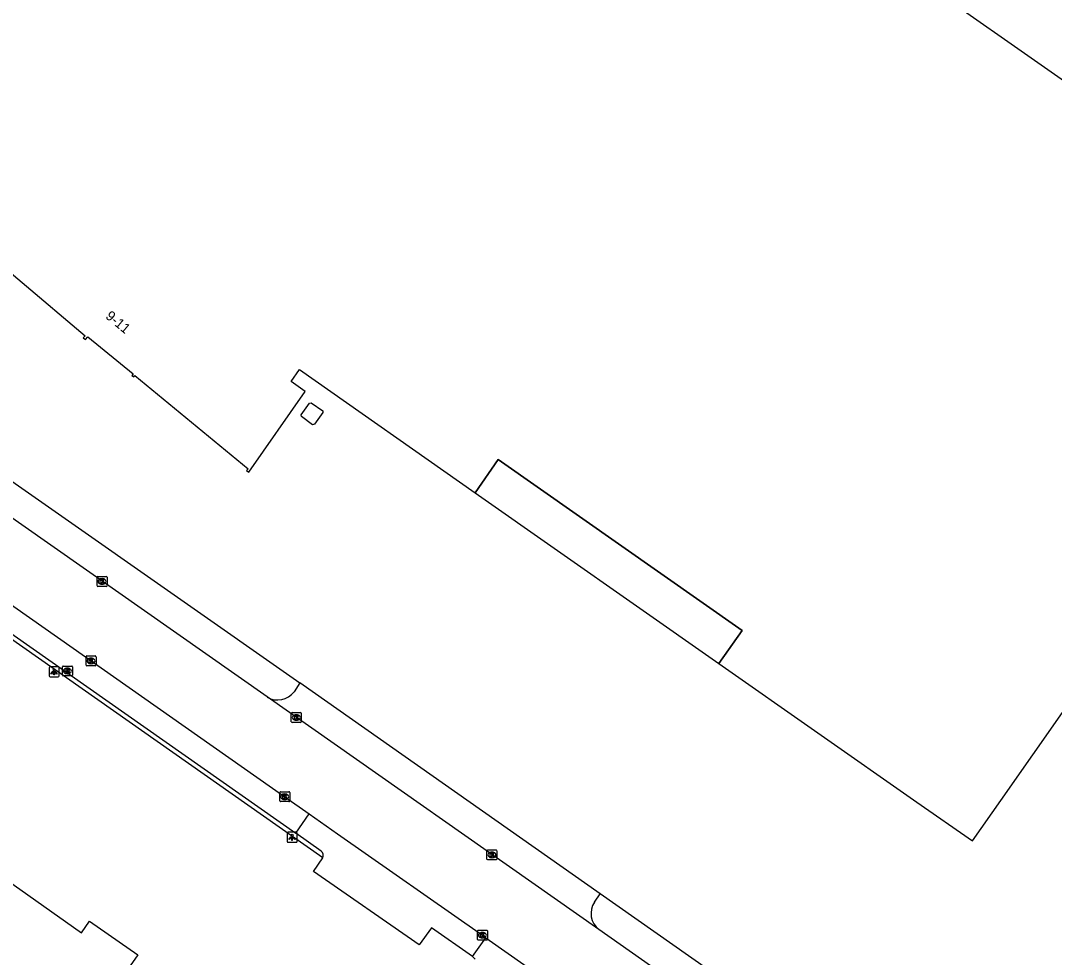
# Model space of a CAD drawing. Extents: x 155018 to 156648, y 383980 to 385733.
# Drawn here: x 155409.7 to 155513.9, y 384753.9 to 384848.3 of the extents above; entities that cross this region are included whole.
import ezdxf

# ---------------------------------------------------------------- set-up
doc = ezdxf.new("R2010")
doc.units = 0
for name, color, linetype in [('IMGEO_Brandkraan', 7, 'Continuous'), ('IMGEO_Kolk', 7, 'Continuous'), ('IMGEO_Lichtpunt', 7, 'Continuous'), ('IMGEO_Pand', 7, 'Continuous'), ('IMGEO_Pand_nummerreeks', 7, 'Continuous'), ('IMGEO_Pand_overbouw', 7, 'Continuous'), ('IMGEO_Parkeervlak_open', 7, 'Continuous'), ('IMGEO_Rijbaan_lokaal_gesloten', 7, 'Continuous'), ('IMGEO_Voetpad_open', 7, 'Continuous')]:
    doc.layers.add(name, color=color, linetype=linetype)

msp = doc.modelspace()

# ---------------------------------------------------------------- linework, layer by layer
at = {"layer": 'IMGEO_Brandkraan'}
for p, q in [((155413.94, 384782.3), (155413.94, 384783.16)), ((155414.02, 384783.23), (155414.87, 384783.23)), ((155414.43, 384783.01), (155414.45, 384783.01)), ((155414.94, 384783.16), (155414.94, 384782.3)), ((155414.87, 384782.23), (155414.02, 384782.23)), ((155414.45, 384782.45), (155414.43, 384782.45))]:
    msp.add_line(p, q, dxfattribs=at)
for points in [[(155413.94, 384782.3), (155413.94, 384783.16)], [(155414.02, 384783.23), (155414.87, 384783.23)], [(155414.94, 384783.16), (155414.94, 384782.3)], [(155414.87, 384782.23), (155414.02, 384782.23)], [(155414.29, 384782.93), (155414.29, 384782.53), (155414.5, 384782.53)], [(155414.52, 384782.93), (155414.29, 384782.93)], [(155414.47, 384782.85), (155414.41, 384782.85), (155414.41, 384782.77)], [(155414.41, 384782.77), (155414.47, 384782.77)], [(155414.48, 384782.7), (155414.41, 384782.7), (155414.41, 384782.61)], [(155414.41, 384782.61), (155414.48, 384782.61)]]:
    msp.add_lwpolyline(points, dxfattribs=at)
for centre, radius, start, end in [((155414.02, 384783.15), 0.0765, 91.552, 178.448), ((155414.02, 384783.15), 0.0765, 91.552, 178.448), ((155414.87, 384783.15), 0.0765, 1.552, 88.448), ((155414.87, 384783.15), 0.0765, 1.552, 88.448), ((155414.02, 384782.3), 0.0765, 181.552, 268.448), ((155414.02, 384782.3), 0.0765, 181.552, 268.448), ((155414.47, 384782.81), 0.0379, 267.8285, 90.9355), ((155414.48, 384782.66), 0.0404, 269.8759, 90.5077), ((155414.51, 384782.78), 0.251, 268.6676, 293.5347), ((155414.52, 384782.78), 0.145, 59.4692, 91.5367), ((155414.55, 384782.83), 0.0922, 285.5137, 58.1501), ((155414.55, 384782.64), 0.105, 301.3115, 78.989), ((155414.87, 384782.3), 0.0765, 271.552, 358.448), ((155414.87, 384782.3), 0.0765, 271.552, 358.448)]:
    msp.add_arc(centre, radius, start, end, dxfattribs=at)
for centre, major_axis, ratio, start_param, end_param in [((155414.43, 384782.73), (-0.387, 0.002), 0.722429, 4.712389, 7.853982), ((155414.45, 384782.73), (-0.39, 0.002), 0.717154, 1.570796, 4.712389)]:
    msp.add_ellipse(centre, major_axis=major_axis, ratio=ratio, start_param=start_param, end_param=end_param, dxfattribs=at)
at = {"layer": 'IMGEO_Kolk'}
for p, q in [((155417.43, 384791.33), (155417.43, 384792.19)), ((155417.5, 384792.26), (155418.36, 384792.26)), ((155417.94, 384791.48), (155417.91, 384791.48)), ((155417.92, 384792.04), (155417.94, 384792.04)), ((155418.43, 384792.19), (155418.43, 384791.33)), ((155418.36, 384791.26), (155417.5, 384791.26)), ((155416.32, 384783.32), (155416.32, 384784.17)), ((155416.39, 384784.24), (155417.24, 384784.24)), ((155417.32, 384784.17), (155417.32, 384783.32)), ((155417.24, 384783.24), (155416.39, 384783.24)), ((155416.8, 384784.02), (155416.83, 384784.02)), ((155416.83, 384783.46), (155416.8, 384783.46)), ((155436.99, 384777.61), (155436.99, 384778.47)), ((155437.07, 384778.54), (155437.92, 384778.54)), ((155437.48, 384778.32), (155437.51, 384778.32)), ((155438, 384778.47), (155438, 384777.61)), ((155437.92, 384777.54), (155437.07, 384777.54)), ((155437.5, 384777.76), (155437.48, 384777.76)), ((155435.9, 384770.56), (155436.76, 384770.56)), ((155435.83, 384769.64), (155435.83, 384770.49)), ((155436.76, 384769.56), (155435.9, 384769.56)), ((155436.34, 384769.78), (155436.31, 384769.78)), ((155436.32, 384770.34), (155436.34, 384770.34)), ((155436.83, 384770.49), (155436.83, 384769.64)), ((155456.7, 384763.76), (155456.7, 384764.62)), ((155456.77, 384764.69), (155457.62, 384764.69)), ((155457.19, 384764.47), (155457.21, 384764.47)), ((155457.7, 384764.62), (155457.7, 384763.76)), ((155457.62, 384763.69), (155456.77, 384763.69)), ((155457.21, 384763.91), (155457.18, 384763.91)), ((155455.74, 384755.68), (155455.74, 384756.53)), ((155455.82, 384756.61), (155456.67, 384756.61)), ((155456.23, 384756.39), (155456.26, 384756.39)), ((155456.74, 384756.53), (155456.74, 384755.68)), ((155456.67, 384755.61), (155455.82, 384755.61)), ((155456.25, 384755.83), (155456.23, 384755.83))]:
    msp.add_line(p, q, dxfattribs=at)
for points in [[(155417.43, 384791.33), (155417.43, 384792.19)], [(155417.5, 384792.26), (155418.36, 384792.26)], [(155417.75, 384791.96), (155417.87, 384791.96), (155417.87, 384791.81), (155418, 384791.96), (155418.17, 384791.96), (155418.02, 384791.81), (155418.17, 384791.56), (155418.02, 384791.56), (155417.94, 384791.72), (155417.87, 384791.66), (155417.87, 384791.56), (155417.75, 384791.56), (155417.75, 384791.96)], [(155418.43, 384792.19), (155418.43, 384791.33)], [(155418.36, 384791.26), (155417.5, 384791.26)], [(155416.32, 384783.32), (155416.32, 384784.17)], [(155416.39, 384784.24), (155417.24, 384784.24)], [(155417.32, 384784.17), (155417.32, 384783.32)], [(155417.24, 384783.24), (155416.39, 384783.24)], [(155416.64, 384783.94), (155416.76, 384783.94), (155416.76, 384783.79), (155416.89, 384783.94), (155417.05, 384783.94), (155416.91, 384783.79), (155417.06, 384783.54), (155416.91, 384783.54), (155416.82, 384783.71), (155416.76, 384783.64), (155416.76, 384783.54), (155416.64, 384783.54), (155416.64, 384783.94)], [(155436.99, 384777.61), (155436.99, 384778.47)], [(155437.07, 384778.54), (155437.92, 384778.54)], [(155437.31, 384778.24), (155437.44, 384778.24), (155437.44, 384778.09), (155437.57, 384778.24), (155437.73, 384778.24), (155437.59, 384778.09), (155437.74, 384777.84), (155437.59, 384777.84), (155437.5, 384778), (155437.44, 384777.94), (155437.44, 384777.84), (155437.31, 384777.84), (155437.31, 384778.24)], [(155438, 384778.47), (155438, 384777.61)], [(155437.92, 384777.54), (155437.07, 384777.54)], [(155435.9, 384770.56), (155436.76, 384770.56)], [(155435.83, 384769.64), (155435.83, 384770.49)], [(155436.76, 384769.56), (155435.9, 384769.56)], [(155436.15, 384770.26), (155436.27, 384770.26), (155436.27, 384770.11), (155436.4, 384770.26), (155436.57, 384770.26), (155436.42, 384770.11), (155436.57, 384769.86), (155436.42, 384769.86), (155436.34, 384770.03), (155436.27, 384769.96), (155436.27, 384769.86), (155436.15, 384769.86), (155436.15, 384770.26)], [(155436.83, 384770.49), (155436.83, 384769.64)], [(155456.7, 384763.76), (155456.7, 384764.62)], [(155456.77, 384764.69), (155457.62, 384764.69)], [(155457.02, 384764.39), (155457.14, 384764.39), (155457.14, 384764.24), (155457.27, 384764.39), (155457.44, 384764.39), (155457.29, 384764.24), (155457.44, 384763.99), (155457.29, 384763.99), (155457.21, 384764.16), (155457.14, 384764.09), (155457.14, 384763.99), (155457.02, 384763.99), (155457.02, 384764.39)], [(155457.7, 384764.62), (155457.7, 384763.76)], [(155457.62, 384763.69), (155456.77, 384763.69)], [(155455.74, 384755.68), (155455.74, 384756.53)], [(155455.82, 384756.61), (155456.67, 384756.61)], [(155456.06, 384756.31), (155456.19, 384756.31), (155456.19, 384756.16), (155456.32, 384756.31), (155456.48, 384756.31), (155456.33, 384756.16), (155456.49, 384755.91), (155456.33, 384755.91), (155456.25, 384756.07), (155456.19, 384756.01), (155456.19, 384755.91), (155456.06, 384755.91), (155456.06, 384756.31)], [(155456.74, 384756.53), (155456.74, 384755.68)], [(155456.67, 384755.61), (155455.82, 384755.61)]]:
    msp.add_lwpolyline(points, dxfattribs=at)
for centre, start, end in [((155417.5, 384792.18), 91.552, 178.448), ((155417.5, 384792.18), 91.552, 178.448), ((155417.5, 384791.33), 181.552, 268.448), ((155417.5, 384791.33), 181.552, 268.448), ((155418.35, 384792.18), 1.552, 88.448), ((155418.35, 384792.18), 1.552, 88.448), ((155418.35, 384791.33), 271.552, 358.448), ((155418.35, 384791.33), 271.552, 358.448), ((155416.39, 384784.17), 91.552, 178.448), ((155416.39, 384784.17), 91.552, 178.448), ((155417.24, 384784.17), 1.552, 88.448), ((155417.24, 384784.17), 1.552, 88.448), ((155416.39, 384783.32), 181.552, 268.448), ((155416.39, 384783.32), 181.552, 268.448), ((155417.24, 384783.32), 271.552, 358.448), ((155417.24, 384783.32), 271.552, 358.448), ((155437.07, 384778.46), 91.552, 178.448), ((155437.07, 384778.46), 91.552, 178.448), ((155437.92, 384778.46), 1.552, 88.448), ((155437.92, 384778.46), 1.552, 88.448), ((155437.07, 384777.62), 181.552, 268.448), ((155437.07, 384777.62), 181.552, 268.448), ((155437.92, 384777.62), 271.552, 358.448), ((155437.92, 384777.62), 271.552, 358.448), ((155435.91, 384770.49), 91.552, 178.448), ((155435.91, 384770.49), 91.552, 178.448), ((155436.75, 384770.49), 1.552, 88.448), ((155436.75, 384770.49), 1.552, 88.448), ((155435.91, 384769.64), 181.552, 268.448), ((155435.91, 384769.64), 181.552, 268.448), ((155436.75, 384769.64), 271.552, 358.448), ((155436.75, 384769.64), 271.552, 358.448), ((155456.77, 384764.62), 91.552, 178.448), ((155456.77, 384764.62), 91.552, 178.448), ((155457.62, 384764.62), 1.552, 88.448), ((155457.62, 384764.62), 1.552, 88.448), ((155456.77, 384763.77), 181.552, 268.448), ((155456.77, 384763.77), 181.552, 268.448), ((155457.62, 384763.77), 271.552, 358.448), ((155457.62, 384763.77), 271.552, 358.448), ((155455.82, 384756.53), 91.552, 178.448), ((155455.82, 384756.53), 91.552, 178.448), ((155456.67, 384756.53), 1.552, 88.448), ((155456.67, 384756.53), 1.552, 88.448), ((155455.82, 384755.68), 181.552, 268.448), ((155455.82, 384755.68), 181.552, 268.448), ((155456.67, 384755.68), 271.552, 358.448), ((155456.67, 384755.68), 271.552, 358.448)]:
    msp.add_arc(centre, 0.0765, start, end, dxfattribs=at)
for centre, major_axis, ratio, start_param, end_param in [((155417.92, 384791.76), (-0.387, 0.002), 0.722429, 4.712389, 7.853982), ((155417.94, 384791.76), (-0.39, 0.002), 0.717154, 1.570796, 4.712389), ((155416.8, 384783.74), (-0.387, 0.002), 0.722429, 4.712389, 7.853982), ((155416.83, 384783.74), (-0.39, 0.002), 0.717154, 1.570796, 4.712389), ((155437.48, 384778.04), (-0.387, 0.002), 0.722429, 4.712389, 7.853982), ((155437.51, 384778.04), (-0.39, 0.002), 0.717154, 1.570796, 4.712389), ((155436.32, 384770.06), (-0.387, 0.002), 0.722429, 4.712389, 7.853982), ((155436.34, 384770.06), (-0.39, 0.002), 0.717154, 1.570796, 4.712389), ((155457.18, 384764.19), (-0.387, 0.002), 0.722429, 4.712389, 7.853982), ((155457.21, 384764.19), (-0.39, 0.002), 0.717154, 1.570796, 4.712389), ((155456.23, 384756.11), (-0.387, 0.002), 0.722429, 4.712389, 7.853982), ((155456.25, 384756.11), (-0.39, 0.002), 0.717154, 1.570796, 4.712389)]:
    msp.add_ellipse(centre, major_axis=major_axis, ratio=ratio, start_param=start_param, end_param=end_param, dxfattribs=at)
at = {"layer": 'IMGEO_Lichtpunt'}
for p, q in [((155412.6, 384783.05), (155412.6, 384782.24)), ((155412.6, 384783.05), (155412.6, 384782.24)), ((155413.5, 384783.15), (155412.69, 384783.15)), ((155413.5, 384783.15), (155412.69, 384783.15)), ((155413.59, 384782.24), (155413.59, 384783.05)), ((155413.59, 384782.24), (155413.59, 384783.05)), ((155412.69, 384782.15), (155413.5, 384782.15)), ((155412.69, 384782.15), (155413.5, 384782.15)), ((155436.57, 384766.37), (155436.57, 384765.56)), ((155436.57, 384766.37), (155436.57, 384765.56)), ((155437.47, 384766.47), (155436.66, 384766.47)), ((155437.47, 384766.47), (155436.66, 384766.47)), ((155437.57, 384765.56), (155437.57, 384766.37)), ((155437.57, 384765.56), (155437.57, 384766.37)), ((155436.66, 384765.47), (155437.47, 384765.47)), ((155436.66, 384765.47), (155437.47, 384765.47))]:
    msp.add_line(p, q, dxfattribs=at)
for points in [[(155412.97, 384782.71), (155413.01, 384782.69), (155412.82, 384782.42), (155412.78, 384782.45), (155412.97, 384782.71)], [(155413.07, 384782.67), (155413.12, 384782.67), (155413.12, 384782.34), (155413.07, 384782.34), (155413.07, 384782.67)], [(155413.18, 384782.69), (155413.22, 384782.71), (155413.41, 384782.45), (155413.37, 384782.42), (155413.18, 384782.69)], [(155436.94, 384766.03), (155436.98, 384766.01), (155436.79, 384765.74), (155436.76, 384765.77), (155436.94, 384766.03)], [(155437.04, 384765.99), (155437.09, 384765.99), (155437.09, 384765.66), (155437.04, 384765.66), (155437.04, 384765.99)], [(155437.15, 384766.01), (155437.19, 384766.03), (155437.38, 384765.77), (155437.34, 384765.74), (155437.15, 384766.01)]]:
    msp.add_lwpolyline(points, dxfattribs=at)
for centre in [(155413.1, 384782.85), (155437.07, 384766.17)]:
    msp.add_circle(centre, 0.0994, dxfattribs=at)
for centre, start, end in [((155412.69, 384783.05), 90, 180), ((155412.69, 384783.05), 90, 180), ((155413.5, 384783.05), 0, 90), ((155413.5, 384783.05), 0, 90), ((155412.69, 384782.24), 180, 270), ((155412.69, 384782.24), 180, 270), ((155413.5, 384782.24), 270, 0), ((155413.5, 384782.24), 270, 360), ((155436.66, 384766.37), 90, 180), ((155436.66, 384766.37), 90, 180), ((155437.47, 384766.37), 0, 90), ((155437.47, 384766.37), 0, 90), ((155436.66, 384765.56), 180, 270), ((155436.66, 384765.56), 180, 270), ((155437.47, 384765.56), 270, 0), ((155437.47, 384765.56), 270, 360)]:
    msp.add_arc(centre, 0.0946, start, end, dxfattribs=at)
at = {"layer": 'IMGEO_Pand'}
for points in [[(155403.49, 384827.27), (155416.22, 384816.52), (155416.04, 384816.29), (155416.25, 384816.12), (155416.49, 384816.42), (155421.05, 384812.67), (155420.92, 384812.52), (155421.12, 384812.36), (155421.24, 384812.52), (155432.66, 384803.11), (155432.49, 384802.93), (155432.7, 384802.77), (155438.4, 384810.89), (155436.96, 384811.9), (155437.8, 384813.1), (155455.51, 384800.69), (155457.83, 384804.03), (155482.39, 384786.81), (155480.06, 384783.49), (155500, 384769.52), (155505.6, 384765.6), (155508.47, 384769.69), (155544.63, 384821.3), (155500, 384852.57)], [(155439.31, 384807.61), (155439.12, 384807.54), (155438.01, 384808.38), (155437.98, 384808.56), (155438.83, 384809.73), (155438.98, 384809.77), (155440.17, 384808.96), (155440.16, 384808.78), (155439.31, 384807.61)], [(155361.29, 384753.68), (155375.95, 384774.63), (155362.67, 384783.95), (155366.73, 384789.73), (155369.6, 384793.83), (155373.4, 384791.12), (155375.33, 384793.83), (155377.96, 384791.99), (155380.25, 384795.27), (155380.07, 384795.4), (155380.3, 384795.72), (155400.99, 384781.22), (155394.99, 384772.67), (155399.4, 384769.58), (155398.61, 384768.48), (155407.05, 384762.52), (155407.85, 384763.68), (155408.25, 384763.39), (155407.44, 384762.27), (155415.86, 384756.33), (155416.67, 384757.5), (155421.52, 384754.12), (155418.63, 384750)]]:
    msp.add_lwpolyline(points, dxfattribs=at)
at = {"layer": 'IMGEO_Pand_overbouw'}
msp.add_lwpolyline([(155457.83, 384804.03), (155455.51, 384800.69), (155480.06, 384783.49), (155482.39, 384786.81)], close=True, dxfattribs=at)
at = {"layer": 'IMGEO_Parkeervlak_open'}
msp.add_lwpolyline([(155455.52, 384753.7), (155455.24, 384753.97)], dxfattribs=at)
at = {"layer": 'IMGEO_Rijbaan_lokaal_gesloten'}
for points in [[(155434.55, 384780.11), (155388.02, 384812.73)], [(155391.66, 384801.39), (155397.71, 384797.16), (155436.33, 384770.06), (155438.8, 384768.32)], [(155467.97, 384756.67), (155434.55, 384780.11)], [(155438.8, 384768.32), (155441.64, 384766.32), (155456.24, 384756.11), (155456.59, 384755.85)], [(155494.89, 384737.79), (155477.48, 384750), (155467.97, 384756.67)], [(155456.59, 384755.85), (155464.92, 384750), (155479.51, 384739.76)]]:
    msp.add_lwpolyline(points, dxfattribs=at)
at = {"layer": 'IMGEO_Voetpad_open'}
for points in [[(155440.15, 384763.9), (155361.77, 384818.95)], [(155388.18, 384816.31), (155437.86, 384781.52)], [(155391, 384798.97), (155395.65, 384795.72), (155437.44, 384766.38)], [(155437.86, 384781.52), (155437.29, 384780.64)], [(155468.11, 384760.26), (155437.86, 384781.52)], [(155437.44, 384766.38), (155438.8, 384768.32)], [(155440.01, 384764.57), (155437.44, 384766.38)], [(155455.24, 384753.97), (155451.1, 384756.85), (155449.87, 384755.13), (155439.23, 384762.53), (155440.15, 384763.9)], [(155467.52, 384759.44), (155468.11, 384760.26)], [(155497.01, 384739.99), (155482.74, 384750), (155468.11, 384760.26)], [(155455.24, 384753.97), (155456.59, 384755.85)]]:
    msp.add_lwpolyline(points, dxfattribs=at)
for centre, radius, start, end in [((155435.62, 384781.89), 2.08, 238.97, 323.1827), ((155439.7, 384764.15), 0.518, 330.7033, 54.3543), ((155469.24, 384758.3), 2.06, 146.5162, 232.2541)]:
    msp.add_arc(centre, radius, start, end, dxfattribs=at)

# ---------------------------------------------------------------- texts
at = {"layer": 'IMGEO_Pand_nummerreeks'}
msp.add_text('9-11', height=1, rotation=320.3742, dxfattribs=at).set_placement((155418.2, 384818.36))

doc.saveas('drawing.dxf')
